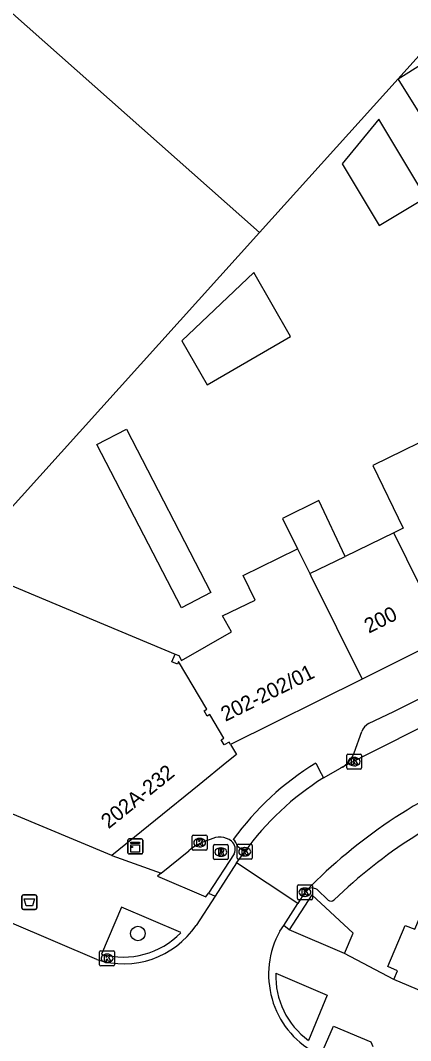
# Model space of a CAD drawing. Extents: x 161771 to 163125, y 382479 to 383177.
# Drawn here: x 162193.7 to 162219.9, y 382635.1 to 382703.5 of the extents above; entities that cross this region are included whole.
import ezdxf

# ---------------------------------------------------------------- set-up
doc = ezdxf.new("R2010")
doc.units = 0
for name, color, linetype in [('IMGEO_Afvalbak', 7, 'Continuous'), ('IMGEO_Boom', 7, 'Continuous'), ('IMGEO_Kast', 7, 'Continuous'), ('IMGEO_Kolk', 7, 'Continuous'), ('IMGEO_Muur', 7, 'Continuous'), ('IMGEO_Pand', 7, 'Continuous'), ('IMGEO_Pand_nummerreeks', 7, 'Continuous'), ('IMGEO_Parkeervlak_open', 7, 'Continuous'), ('IMGEO_Rijbaan_lokaal_open', 7, 'Continuous'), ('IMGEO_Rioolput', 7, 'Continuous'), ('IMGEO_Voetpad_open', 7, 'Continuous')]:
    doc.layers.add(name, color=color, linetype=linetype)

msp = doc.modelspace()

# ---------------------------------------------------------------- linework, layer by layer
at = {"layer": 'IMGEO_Afvalbak'}
for p, q in [((162193.926, 382644.857), (162194.716, 382644.857)), ((162194.716, 382644.857), (162193.926, 382644.857)), ((162193.826, 382643.957), (162193.826, 382644.757)), ((162193.826, 382644.757), (162193.826, 382643.957)), ((162194.816, 382644.757), (162194.816, 382643.957)), ((162194.816, 382643.957), (162194.816, 382644.757)), ((162194.716, 382643.857), (162193.926, 382643.857)), ((162193.926, 382643.857), (162194.716, 382643.857))]:
    msp.add_line(p, q, dxfattribs=at)
msp.add_lwpolyline([(162193.969, 382644.571), (162194.673, 382644.571), (162194.524, 382644.101), (162194.118, 382644.101), (162193.969, 382644.571)], dxfattribs=at)
for centre, start, end in [((162193.926, 382644.757), 90, 180), ((162193.926, 382644.757), 90, 180), ((162194.716, 382644.757), 0, 90), ((162194.716, 382644.757), 360, 90), ((162193.926, 382643.957), 180, 270), ((162193.926, 382643.957), 180, 270), ((162194.716, 382643.957), 270, 0), ((162194.716, 382643.957), 270, 0)]:
    msp.add_arc(centre, 0.1, start, end, dxfattribs=at)
at = {"layer": 'IMGEO_Boom'}
msp.add_circle((162201.607, 382642.256), 0.489, dxfattribs=at)
at = {"layer": 'IMGEO_Kast'}
for p, q in [((162200.93, 382647.665), (162200.93, 382648.506)), ((162200.93, 382648.506), (162200.93, 382647.665)), ((162201.005, 382648.59), (162201.846, 382648.59)), ((162201.846, 382648.59), (162201.005, 382648.59)), ((162201.93, 382648.515), (162201.93, 382647.674)), ((162201.93, 382647.674), (162201.93, 382648.515)), ((162201.855, 382647.59), (162201.014, 382647.59)), ((162201.014, 382647.59), (162201.855, 382647.59))]:
    msp.add_line(p, q, dxfattribs=at)
for points in [[(162201.125, 382648.38), (162201.725, 382648.38), (162201.725, 382648.295), (162201.125, 382648.295), (162201.125, 382648.38)], [(162201.125, 382648.205), (162201.725, 382648.205), (162201.725, 382647.716), (162201.125, 382647.716), (162201.125, 382648.205)]]:
    msp.add_lwpolyline(points, dxfattribs=at)
msp.add_circle((162201.209, 382648.054), 0.0377, dxfattribs=at)
for centre, start, end in [((162201.008, 382648.512), 92.4484, 184.28452), ((162201.008, 382648.512), 92.4484, 184.28452), ((162201.852, 382648.512), 2.4484, 94.28452), ((162201.852, 382648.512), 2.4484, 94.28452), ((162201.008, 382647.668), 182.4484, 274.28452), ((162201.008, 382647.668), 182.4484, 274.28452), ((162201.852, 382647.668), 272.4484, 4.28452), ((162201.852, 382647.668), 272.4484, 4.28452)]:
    msp.add_arc(centre, 0.0779, start, end, dxfattribs=at)
at = {"layer": 'IMGEO_Kolk'}
for p, q in [((162215.625, 382653.349), (162215.625, 382654.201)), ((162215.7, 382654.275), (162216.552, 382654.275)), ((162216.113, 382654.055), (162216.138, 382654.055)), ((162216.626, 382654.201), (162216.626, 382653.349)), ((162216.552, 382653.275), (162215.7, 382653.275)), ((162216.136, 382653.495), (162216.111, 382653.495)), ((162205.251, 382647.92), (162205.251, 382648.772)), ((162205.326, 382648.846), (162206.178, 382648.846)), ((162205.739, 382648.626), (162205.764, 382648.626)), ((162206.252, 382648.772), (162206.252, 382647.92)), ((162208.351, 382648.237), (162209.203, 382648.237)), ((162206.178, 382647.846), (162205.326, 382647.846)), ((162205.762, 382648.066), (162205.737, 382648.066)), ((162208.276, 382647.311), (162208.276, 382648.163)), ((162208.764, 382648.017), (162208.789, 382648.017)), ((162209.277, 382648.163), (162209.277, 382647.311)), ((162209.203, 382647.237), (162208.351, 382647.237)), ((162208.787, 382647.457), (162208.762, 382647.457)), ((162212.315, 382644.597), (162212.315, 382645.449)), ((162212.39, 382645.523), (162213.242, 382645.523)), ((162213.316, 382645.449), (162213.316, 382644.597)), ((162212.803, 382645.303), (162212.828, 382645.303)), ((162213.242, 382644.523), (162212.39, 382644.523)), ((162212.826, 382644.743), (162212.801, 382644.743)), ((162199.04, 382640.164), (162199.04, 382641.016)), ((162199.115, 382641.09), (162199.967, 382641.09)), ((162199.528, 382640.87), (162199.553, 382640.87)), ((162200.041, 382641.016), (162200.041, 382640.164)), ((162199.967, 382640.09), (162199.115, 382640.09)), ((162199.551, 382640.31), (162199.526, 382640.31))]:
    msp.add_line(p, q, dxfattribs=at)
for points in [[(162215.625, 382653.349), (162215.625, 382654.201)], [(162215.7, 382654.275), (162216.552, 382654.275)], [(162215.946, 382653.975), (162216.069, 382653.975), (162216.069, 382653.824), (162216.199, 382653.975), (162216.363, 382653.975), (162216.217, 382653.824), (162216.37, 382653.575), (162216.218, 382653.575), (162216.133, 382653.739), (162216.069, 382653.672), (162216.069, 382653.575), (162215.946, 382653.575), (162215.946, 382653.975)], [(162216.626, 382654.201), (162216.626, 382653.349)], [(162216.552, 382653.275), (162215.7, 382653.275)], [(162205.251, 382647.92), (162205.251, 382648.772)], [(162205.326, 382648.846), (162206.178, 382648.846)], [(162205.572, 382648.546), (162205.695, 382648.546), (162205.695, 382648.395), (162205.825, 382648.546), (162205.989, 382648.546), (162205.843, 382648.395), (162205.996, 382648.146), (162205.844, 382648.146), (162205.759, 382648.31), (162205.695, 382648.243), (162205.695, 382648.146), (162205.572, 382648.146), (162205.572, 382648.546)], [(162206.252, 382648.772), (162206.252, 382647.92)], [(162208.351, 382648.237), (162209.203, 382648.237)], [(162206.178, 382647.846), (162205.326, 382647.846)], [(162208.276, 382647.311), (162208.276, 382648.163)], [(162208.597, 382647.937), (162208.72, 382647.937), (162208.72, 382647.786), (162208.85, 382647.937), (162209.014, 382647.937), (162208.868, 382647.786), (162209.021, 382647.537), (162208.869, 382647.537), (162208.784, 382647.701), (162208.72, 382647.634), (162208.72, 382647.537), (162208.597, 382647.537), (162208.597, 382647.937)], [(162209.277, 382648.163), (162209.277, 382647.311)], [(162209.203, 382647.237), (162208.351, 382647.237)], [(162212.315, 382644.597), (162212.315, 382645.449)], [(162212.39, 382645.523), (162213.242, 382645.523)], [(162213.316, 382645.449), (162213.316, 382644.597)], [(162212.636, 382645.223), (162212.759, 382645.223), (162212.759, 382645.072), (162212.889, 382645.223), (162213.053, 382645.223), (162212.907, 382645.072), (162213.06, 382644.823), (162212.908, 382644.823), (162212.823, 382644.987), (162212.759, 382644.92), (162212.759, 382644.823), (162212.636, 382644.823), (162212.636, 382645.223)], [(162213.242, 382644.523), (162212.39, 382644.523)], [(162199.04, 382640.164), (162199.04, 382641.016)], [(162199.115, 382641.09), (162199.967, 382641.09)], [(162199.361, 382640.79), (162199.484, 382640.79), (162199.484, 382640.639), (162199.614, 382640.79), (162199.778, 382640.79), (162199.632, 382640.639), (162199.785, 382640.39), (162199.633, 382640.39), (162199.548, 382640.554), (162199.484, 382640.487), (162199.484, 382640.39), (162199.361, 382640.39), (162199.361, 382640.79)], [(162200.041, 382641.016), (162200.041, 382640.164)], [(162199.967, 382640.09), (162199.115, 382640.09)]]:
    msp.add_lwpolyline(points, dxfattribs=at)
for centre, start, end in [((162215.702, 382654.199), 91.55205, 178.44795), ((162215.702, 382654.199), 91.55205, 178.44795), ((162216.55, 382654.199), 1.55205, 88.44795), ((162216.55, 382654.199), 1.55205, 88.44795), ((162215.702, 382653.351), 181.55205, 268.44795), ((162215.702, 382653.351), 181.55205, 268.44795), ((162216.55, 382653.351), 271.55205, 358.44795), ((162216.55, 382653.351), 271.55205, 358.44795), ((162205.328, 382648.77), 91.55205, 178.44795), ((162205.328, 382648.77), 91.55205, 178.44795), ((162206.176, 382648.77), 1.55205, 88.44795), ((162206.176, 382648.77), 1.55205, 88.44795), ((162208.353, 382648.161), 91.55205, 178.44795), ((162208.353, 382648.161), 91.55205, 178.44795), ((162209.201, 382648.161), 1.55205, 88.44795), ((162209.201, 382648.161), 1.55205, 88.44795), ((162205.328, 382647.922), 181.55205, 268.44795), ((162205.328, 382647.922), 181.55205, 268.44795), ((162206.176, 382647.922), 271.55205, 358.44795), ((162206.176, 382647.922), 271.55205, 358.44795), ((162208.353, 382647.313), 181.55205, 268.44795), ((162208.353, 382647.313), 181.55205, 268.44795), ((162209.201, 382647.313), 271.55205, 358.44795), ((162209.201, 382647.313), 271.55205, 358.44795), ((162212.392, 382645.447), 91.55205, 178.44795), ((162212.392, 382645.447), 91.55205, 178.44795), ((162213.24, 382645.447), 1.55205, 88.44795), ((162213.24, 382645.447), 1.55205, 88.44795), ((162212.392, 382644.599), 181.55205, 268.44795), ((162212.392, 382644.599), 181.55205, 268.44795), ((162213.24, 382644.599), 271.55205, 358.44795), ((162213.24, 382644.599), 271.55205, 358.44795), ((162199.117, 382641.014), 91.55205, 178.44795), ((162199.117, 382641.014), 91.55205, 178.44795), ((162199.965, 382641.014), 1.55205, 88.44795), ((162199.965, 382641.014), 1.55205, 88.44795), ((162199.117, 382640.166), 181.55205, 268.44795), ((162199.117, 382640.166), 181.55205, 268.44795), ((162199.965, 382640.166), 271.55205, 358.44795), ((162199.965, 382640.166), 271.55205, 358.44795)]:
    msp.add_arc(centre, 0.0765, start, end, dxfattribs=at)
for centre, major_axis, ratio, start_param, end_param in [((162216.112, 382653.775), (-0.387, 0.002), 0.722429, 4.712389, 7.853982), ((162216.137, 382653.775), (-0.39, 0.002), 0.717154, 1.570796, 4.712389), ((162205.738, 382648.346), (-0.387, 0.002), 0.722429, 4.712389, 7.853982), ((162205.763, 382648.346), (-0.39, 0.002), 0.717154, 1.570796, 4.712389), ((162208.763, 382647.737), (-0.387, 0.002), 0.722429, 4.712389, 7.853982), ((162208.788, 382647.737), (-0.39, 0.002), 0.717154, 1.570796, 4.712389), ((162212.802, 382645.023), (-0.387, 0.002), 0.722429, 4.712389, 7.853982), ((162212.827, 382645.023), (-0.39, 0.002), 0.717154, 1.570796, 4.712389), ((162199.527, 382640.59), (-0.387, 0.002), 0.722429, 4.712389, 7.853982), ((162199.552, 382640.59), (-0.39, 0.002), 0.717154, 1.570796, 4.712389)]:
    msp.add_ellipse(centre, major_axis=major_axis, ratio=ratio, start_param=start_param, end_param=end_param, dxfattribs=at)
at = {"layer": 'IMGEO_Muur'}
for points in [[(162221.697, 382702.443), (162219.069, 382699.536)], [(162219.069, 382699.536), (162209.762, 382689.239)]]:
    msp.add_lwpolyline(points, dxfattribs=at)
at = {"layer": 'IMGEO_Pand'}
for points in [[(162164.832, 382678.395), (162165.639, 382678.074), (162190.797, 382706.034), (162209.762, 382689.239)], [(162219.069, 382699.536), (162222.264, 382701.539), (162223.85, 382699.01)], [(162224.871, 382697.383), (162221.676, 382695.379), (162219.069, 382699.536)], [(162217.794, 382689.716), (162220.926, 382691.589), (162217.782, 382696.846), (162215.321, 382693.852), (162217.794, 382689.716)], [(162209.762, 382689.239), (162189.675, 382667.014)], [(162209.378, 382686.557), (162204.547, 382681.981), (162206.253, 382679.025), (162211.858, 382682.26), (162209.378, 382686.557)], [(162206.511, 382665.108), (162204.529, 382664.08), (162198.853, 382675.022), (162200.833, 382676.049), (162206.511, 382665.108)], [(162222.49, 382676.115), (162217.379, 382673.633), (162219.422, 382669.427), (162218.775, 382669.113)], [(162215.525, 382667.535), (162213.749, 382671.274), (162211.31, 382670.063), (162212.32, 382668.028)], [(162218.775, 382669.113), (162215.525, 382667.535)], [(162222.263, 382662.095), (162218.775, 382669.113)], [(162204.11, 382660.982), (162204.354, 382660.88), (162204.538, 382660.563), (162207.901, 382662.471), (162207.296, 382663.538), (162209.482, 382664.6), (162208.676, 382666.258), (162211.035, 382667.404), (162212.32, 382668.028)], [(162212.32, 382668.028), (162213.141, 382666.377)], [(162213.141, 382666.377), (162215.525, 382667.535)], [(162189.675, 382667.014), (162198.614, 382663.288), (162204.11, 382660.982)], [(162213.141, 382666.377), (162213.219, 382666.23), (162216.656, 382659.313)], [(162222.263, 382662.095), (162216.656, 382659.313)], [(162207.825, 382654.931), (162207.726, 382655.072), (162207.388, 382654.892), (162207.2, 382655.246), (162207.386, 382655.345), (162206.443, 382656.937), (162206.263, 382656.83), (162206.059, 382657.174), (162206.239, 382657.281), (162204.337, 382660.489), (162204.263, 382660.313), (162203.894, 382660.467), (162204.11, 382660.982)], [(162216.656, 382659.313), (162207.825, 382654.931)], [(162199.862, 382647.487), (162181.94, 382654.954)], [(162207.825, 382654.931), (162208.22, 382654.26), (162207.575, 382653.731), (162205.718, 382652.21), (162199.862, 382647.487)], [(162218.779, 382639.183), (162219.028, 382639.763), (162218.383, 382640.035), (162219.545, 382642.793), (162220.201, 382642.544), (162221.749, 382646.182)], [(162224.667, 382636.684), (162218.779, 382639.183)]]:
    msp.add_lwpolyline(points, dxfattribs=at)
at = {"layer": 'IMGEO_Parkeervlak_open'}
for points in [[(162221.467, 382702.189), (162219.069, 382699.536)], [(162219.069, 382699.536), (162209.762, 382689.239)]]:
    msp.add_lwpolyline(points, dxfattribs=at)
at = {"layer": 'IMGEO_Rijbaan_lokaal_open'}
for points in [[(162259.018, 382675.401), (162215.227, 382653.35)], [(162214.056, 382652.688), (162215.202, 382653.338), (162215.227, 382653.35)], [(162208.233, 382646.982), (162208.777, 382647.737)], [(162208.233, 382646.982), (162206.789, 382644.765)], [(162212.344, 382644.256), (162208.233, 382646.982)], [(162206.789, 382644.765), (162205.509, 382642.799)], [(162212.961, 382645.173), (162212.816, 382645.023), (162212.344, 382644.256)], [(162211.392, 382642.801), (162212.344, 382644.256)], [(162198.856, 382640.517), (162193.15, 382642.947)], [(162211.137, 382642.412), (162211.392, 382642.801)]]:
    msp.add_lwpolyline(points, dxfattribs=at)
for centre, radius, start, end in [((162238.264, 382620.35), 35.445, 111.62248, 123.92902), ((162224.159, 382636.625), 18.976, 122.16993, 144.15723), ((162238.247, 382620.356), 35.43, 123.91271, 135.5369), ((162200.669, 382646.071), 5.842, 251.923, 325.94126), ((162216.334, 382639.506), 5.954, 150.78953, 241.09567)]:
    msp.add_arc(centre, radius, start, end, dxfattribs=at)
at = {"layer": 'IMGEO_Rioolput'}
for p, q in [((162206.747, 382648.215), (162207.599, 382648.215)), ((162206.672, 382647.289), (162206.672, 382648.141)), ((162207.16, 382647.995), (162207.185, 382647.995)), ((162207.673, 382648.141), (162207.673, 382647.289)), ((162207.599, 382647.215), (162206.747, 382647.215)), ((162207.183, 382647.435), (162207.158, 382647.435))]:
    msp.add_line(p, q, dxfattribs=at)
for points in [[(162206.747, 382648.215), (162207.599, 382648.215)], [(162206.672, 382647.289), (162206.672, 382648.141)], [(162207.261, 382647.913), (162207.009, 382647.915), (162207.009, 382647.515)], [(162207.009, 382647.515), (162207.133, 382647.515), (162207.133, 382647.677), (162207.144, 382647.677)], [(162207.187, 382647.834), (162207.133, 382647.834), (162207.133, 382647.753)], [(162207.133, 382647.753), (162207.185, 382647.753)], [(162207.191, 382647.648), (162207.262, 382647.515), (162207.402, 382647.515), (162207.337, 382647.641)], [(162207.673, 382648.141), (162207.673, 382647.289)], [(162207.599, 382647.215), (162206.747, 382647.215)]]:
    msp.add_lwpolyline(points, dxfattribs=at)
for centre, radius, start, end in [((162206.749, 382648.139), 0.0765, 91.55205, 178.44795), ((162206.749, 382648.139), 0.0765, 91.55205, 178.44795), ((162207.597, 382648.139), 0.0765, 1.55205, 88.44795), ((162207.597, 382648.139), 0.0765, 1.55205, 88.44795), ((162207.143, 382647.624), 0.0533, 26.02933, 88.69889), ((162207.169, 382647.942), 0.19, 274.7715, 282.96867), ((162207.193, 382647.738), 0.0964, 77.00612, 93.18647), ((162207.207, 382647.795), 0.0378, 276.66336, 79.67722), ((162207.26, 382647.803), 0.109, 350.36119, 89.41601), ((162207.258, 382647.803), 0.112, 277.58423, 350.98172), ((162207.242, 382647.588), 0.108, 29.51342, 73.79051), ((162206.749, 382647.291), 0.0765, 181.55205, 268.44795), ((162206.749, 382647.291), 0.0765, 181.55205, 268.44795), ((162207.597, 382647.291), 0.0765, 271.55205, 358.44795), ((162207.597, 382647.291), 0.0765, 271.55205, 358.44795)]:
    msp.add_arc(centre, radius, start, end, dxfattribs=at)
for centre, major_axis, ratio, start_param, end_param in [((162207.159, 382647.715), (-0.387, 0.002), 0.722429, 4.712389, 7.853982), ((162207.184, 382647.715), (-0.39, 0.002), 0.717154, 1.570796, 4.712389)]:
    msp.add_ellipse(centre, major_axis=major_axis, ratio=ratio, start_param=start_param, end_param=end_param, dxfattribs=at)
at = {"layer": 'IMGEO_Voetpad_open'}
for points in [[(162217.093, 382656.32), (162218.779, 382657.135), (162225.558, 382660.519), (162255.686, 382675.69)], [(162216.129, 382654.367), (162216.632, 382655.789)], [(162213.543, 382653.673), (162213.904, 382652.98), (162214.056, 382652.688)], [(162203.17, 382646.308), (162205.019, 382647.798)], [(162208.059, 382647.587), (162206.337, 382644.959)], [(162208.777, 382647.737), (162208.286, 382648.093)], [(162199.862, 382647.487), (162203.17, 382646.308)], [(162203.17, 382646.308), (162202.92, 382646.107), (162206.178, 382644.716), (162206.337, 382644.959)], [(162206.337, 382644.959), (162206.789, 382644.765)], [(162215.471, 382640.922), (162216.062, 382642.269), (162213.273, 382644.841), (162211.764, 382642.503)], [(162214.372, 382644.499), (162213.633, 382645.195)], [(162204.494, 382642.312), (162200.505, 382644.023), (162199.171, 382640.874)], [(162211.764, 382642.503), (162211.392, 382642.801)], [(162215.471, 382640.922), (162211.764, 382642.503)], [(162218.779, 382639.183), (162215.471, 382640.922)], [(162210.862, 382639.6), (162214.304, 382638.123), (162213.052, 382635.093)], [(162213.877, 382634.092), (162214.74, 382636.051), (162217.245, 382634.989), (162217.38, 382634.684)]]:
    msp.add_lwpolyline(points, dxfattribs=at)
for centre, radius, start, end in [((162217.503, 382655.499), 0.918, 116.51649, 161.55622), ((162214.368, 382655.02), 1.878, 297.21522, 339.64371), ((162223.563, 382637.296), 19.199, 121.46068, 144.111), ((162238.495, 382619.932), 34.156, 111.11559, 133.98579), ((162207.489, 382644.825), 3.865, 105.53054, 129.71963), ((162207.093, 382647.45), 1.271, 51.06332, 120.18802), ((162207.469, 382647.914), 0.674, 331.00685, 51.17298), ((162207.523, 382647.944), 0.777, 11.02207, 51.30932), ((162213.31, 382644.786), 0.521, 51.69755, 132.05262), ((162214.567, 382644.751), 0.319, 232.22282, 310.34223), ((162200.617, 382646.094), 5.417, 254.52175, 315.71325), ((162216.184, 382639.401), 5.326, 177.85342, 233.97782)]:
    msp.add_arc(centre, radius, start, end, dxfattribs=at)

# ---------------------------------------------------------------- texts
at = {"layer": 'IMGEO_Pand_nummerreeks'}
for s, rotation, p in [('200', 26.39044, (162217.108, 382662.349)), ('202-202/01', 26.39044, (162207.487, 382656.438)), ('202A-232', 38.88665, (162199.638, 382649.233))]:
    msp.add_text(s, height=1, rotation=rotation, dxfattribs=at).set_placement(p)

doc.saveas('drawing.dxf')
